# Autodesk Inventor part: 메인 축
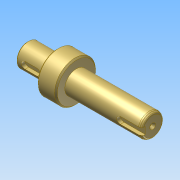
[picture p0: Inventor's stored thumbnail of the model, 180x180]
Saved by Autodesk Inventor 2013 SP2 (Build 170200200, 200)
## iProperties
Created: 2026-07
Part Number: 메인 축
Material: Generic
Document SubType Name: Modeling
Designer: a
Density: 1 g/cm^3
Author: a
변환 표준: STEP AP214IS
전처리기: Build: 200, Release: 2013 SP2 Update 6 - Date: Thu 07/17/2014
전송 단위: 밀리미터
불확실성: 0.01
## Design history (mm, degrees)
node "메인 축1"
node "솔리드1"
node "기준1"
